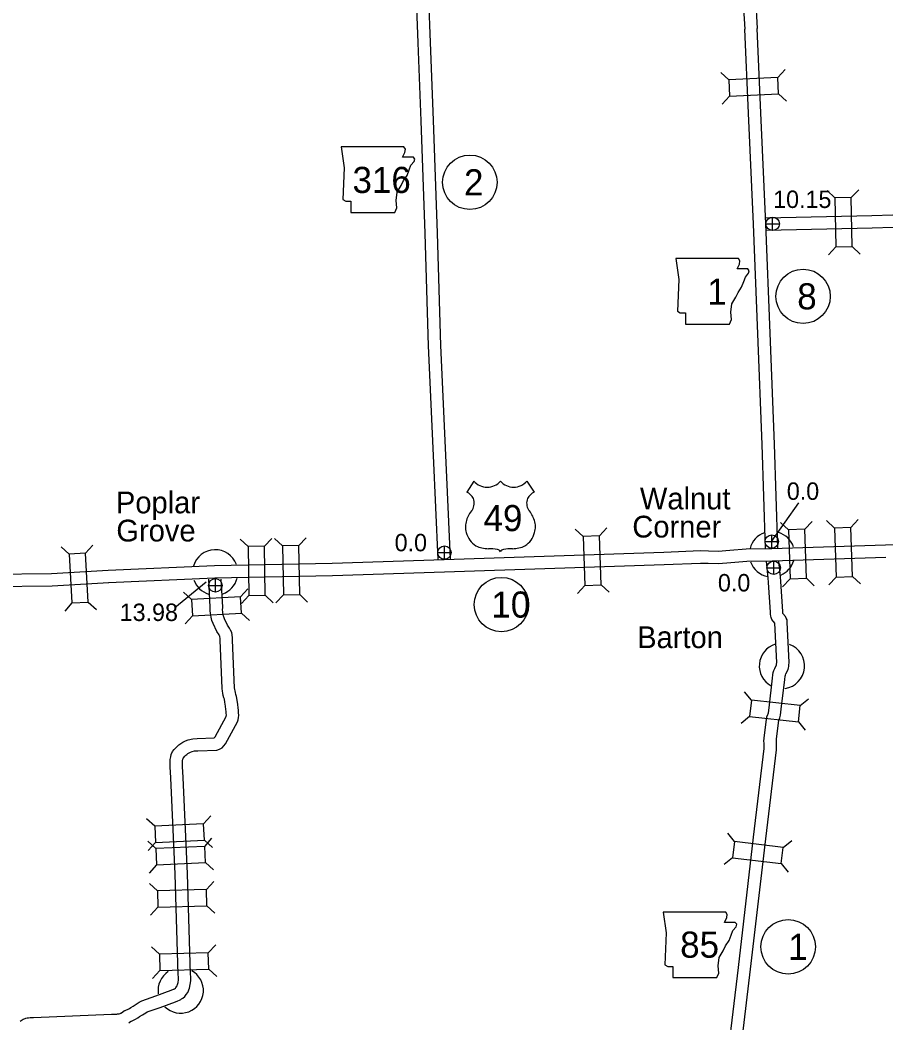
# Model space of a CAD drawing. Extents: x -939622 to -934222, y 1383701 to 1385301.
# Drawn here: x -935826.6 to -935763.6, y 1384033.1 to 1384106.1 of the extents above; entities that cross this region are included whole.
import ezdxf

# ---------------------------------------------------------------- set-up
doc = ezdxf.new("R2010")
doc.units = 0
for name, color, linetype in [('Level 10', 7, 'Continuous'), ('Level 15', 7, 'Continuous'), ('Level 20', 7, 'Continuous'), ('Level 21', 7, 'Continuous'), ('Level 22', 7, 'Continuous'), ('Level 24', 7, 'Continuous'), ('Level 25', 7, 'Continuous'), ('Level 26', 7, 'Continuous'), ('Level 27', 7, 'Continuous')]:
    doc.layers.add(name, color=color, linetype=linetype)

msp = doc.modelspace()

# ---------------------------------------------------------------- linework, layer by layer
at = {"layer": 'Level 10'}
for points in [[(-935774.237, 1384115.055), (-935773.997, 1384107.704), (-935773.868, 1384105.431)], [(-935773.338, 1384115.111), (-935773.098, 1384107.744), (-935772.969, 1384105.482)], [(-935797.116, 1384114.281), (-935797.116, 1384114.271), (-935796.897, 1384107.678), (-935796.77, 1384104.464)], [(-935798.016, 1384114.251), (-935798.015, 1384114.226), (-935797.797, 1384107.646), (-935797.669, 1384104.428)], [(-935772.353, 1384067.639), (-935772.602, 1384075.207), (-935772.91, 1384083.272), (-935773.241, 1384091.235), (-935773.588, 1384099.309), (-935773.868, 1384105.436)], [(-935771.454, 1384067.666), (-935771.703, 1384075.239), (-935772.011, 1384083.308), (-935772.342, 1384091.273), (-935772.689, 1384099.348), (-935772.969, 1384105.477)], [(-935797.669, 1384104.43), (-935797.46, 1384098.764), (-935797.146, 1384090.566), (-935796.911, 1384082.383), (-935796.547, 1384074.399), (-935796.21, 1384066.836)], [(-935796.77, 1384104.463), (-935796.56, 1384098.798), (-935796.247, 1384090.596), (-935796.012, 1384082.416), (-935795.648, 1384074.439), (-935795.311, 1384066.89)], [(-935772.345, 1384091.713), (-935764.621, 1384091.871)], [(-935764.625, 1384091.871), (-935756.982, 1384092.107)], [(-935772.318, 1384090.814), (-935764.602, 1384090.971)], [(-935764.598, 1384090.971), (-935756.947, 1384091.207)], [(-935774.335, 1384037.15), (-935773.234, 1384046.628), (-935772.461, 1384053.102), (-935772.446, 1384053.233), (-935772.446, 1384053.268), (-935772.45, 1384053.37), (-935772.465, 1384053.505), (-935772.47, 1384053.611), (-935772.448, 1384053.86), (-935772.258, 1384055.401), (-935772.183, 1384055.57), (-935772.16, 1384055.618), (-935772.142, 1384055.687), (-935772.103, 1384056.059), (-935771.848, 1384058.212), (-935771.816, 1384058.463), (-935771.795, 1384058.63), (-935771.752, 1384058.759), (-935771.682, 1384058.913), (-935771.553, 1384059.177), (-935771.552, 1384059.179), (-935771.549, 1384059.196), (-935771.546, 1384059.23), (-935771.539, 1384059.348), (-935771.675, 1384062.212), (-935771.903, 1384062.472), (-935771.95, 1384062.618), (-935771.968, 1384062.709), (-935771.993, 1384062.872), (-935772.002, 1384063.006), (-935772.148, 1384065.169), (-935772.174, 1384065.504), (-935772.291, 1384066.698)], [(-935773.441, 1384037.047), (-935772.34, 1384046.523), (-935771.567, 1384052.999), (-935771.546, 1384053.183), (-935771.546, 1384053.287), (-935771.553, 1384053.438), (-935771.567, 1384053.572), (-935771.568, 1384053.592), (-935771.553, 1384053.766), (-935771.381, 1384055.157), (-935771.363, 1384055.197), (-935771.309, 1384055.314), (-935771.255, 1384055.526), (-935771.208, 1384055.958), (-935770.955, 1384058.103), (-935770.923, 1384058.349), (-935770.913, 1384058.43), (-935770.868, 1384058.528), (-935770.715, 1384058.842), (-935770.679, 1384058.956), (-935770.657, 1384059.066), (-935770.648, 1384059.16), (-935770.638, 1384059.344), (-935770.777, 1384062.286), (-935770.79, 1384062.453), (-935770.843, 1384062.579), (-935770.898, 1384062.691), (-935771.088, 1384062.907), (-935771.098, 1384062.972), (-935771.104, 1384063.067), (-935771.25, 1384065.234), (-935771.277, 1384065.583), (-935771.389, 1384066.725)], [(-935815.314, 1384035.654), (-935815.276, 1384035.714), (-935815.196, 1384035.817), (-935815.151, 1384035.916), (-935815.124, 1384036.074), (-935815.096, 1384036.262), (-935815.095, 1384036.457), (-935815.106, 1384036.644), (-935815.321, 1384043.941), (-935815.653, 1384050.947), (-935815.697, 1384051.762), (-935815.695, 1384052.093), (-935815.685, 1384052.289), (-935815.649, 1384052.497), (-935815.613, 1384052.655), (-935815.515, 1384052.869), (-935815.402, 1384053.008), (-935815.29, 1384053.131), (-935815.189, 1384053.241), (-935815.064, 1384053.354), (-935814.93, 1384053.459), (-935814.781, 1384053.55), (-935814.585, 1384053.643), (-935814.375, 1384053.727), (-935814.053, 1384053.806), (-935813.727, 1384053.827), (-935812.487, 1384053.863), (-935812.47, 1384053.882), (-935812.419, 1384053.943), (-935811.62, 1384055.423), (-935811.615, 1384055.459), (-935811.606, 1384055.527), (-935811.612, 1384055.655), (-935811.62, 1384055.782), (-935811.64, 1384055.932), (-935811.671, 1384056.173), (-935811.709, 1384056.47), (-935811.75, 1384056.677), (-935811.777, 1384056.78), (-935811.827, 1384056.952), (-935811.858, 1384057.112), (-935811.887, 1384057.273), (-935811.898, 1384057.465), (-935812.065, 1384060.983), (-935812.058, 1384061.122), (-935812.069, 1384061.213), (-935812.079, 1384061.263), (-935812.095, 1384061.299), (-935812.139, 1384061.373), (-935812.301, 1384061.616), (-935812.57, 1384062.181), (-935812.656, 1384062.405), (-935812.682, 1384062.53), (-935812.709, 1384062.652), (-935812.737, 1384062.789), (-935812.761, 1384062.935), (-935812.784, 1384063.118), (-935812.773, 1384063.376), (-935812.882, 1384065.408)], [(-935814.635, 1384035.046), (-935814.54, 1384035.195), (-935814.421, 1384035.348), (-935814.284, 1384035.648), (-935814.235, 1384035.932), (-935814.197, 1384036.193), (-935814.195, 1384036.48), (-935814.206, 1384036.684), (-935814.422, 1384043.975), (-935814.754, 1384050.993), (-935814.797, 1384051.783), (-935814.795, 1384052.067), (-935814.788, 1384052.19), (-935814.766, 1384052.322), (-935814.756, 1384052.365), (-935814.745, 1384052.39), (-935814.721, 1384052.42), (-935814.626, 1384052.523), (-935814.555, 1384052.601), (-935814.484, 1384052.665), (-935814.415, 1384052.719), (-935814.353, 1384052.757), (-935814.225, 1384052.817), (-935814.099, 1384052.868), (-935813.916, 1384052.913), (-935813.685, 1384052.928), (-935812.293, 1384052.969), (-935812.094, 1384053.032), (-935811.92, 1384053.15), (-935811.791, 1384053.291), (-935811.67, 1384053.436), (-935810.803, 1384055.041), (-935810.744, 1384055.173), (-935810.722, 1384055.345), (-935810.704, 1384055.489), (-935810.713, 1384055.703), (-935810.724, 1384055.87), (-935810.747, 1384056.05), (-935810.778, 1384056.288), (-935810.82, 1384056.614), (-935810.872, 1384056.878), (-935810.909, 1384057.02), (-935810.951, 1384057.164), (-935810.973, 1384057.278), (-935810.992, 1384057.38), (-935811, 1384057.513), (-935811.164, 1384060.98), (-935811.155, 1384061.154), (-935811.18, 1384061.357), (-935811.216, 1384061.535), (-935811.293, 1384061.711), (-935811.378, 1384061.854), (-935811.517, 1384062.062), (-935811.742, 1384062.536), (-935811.79, 1384062.661), (-935811.802, 1384062.716), (-935811.828, 1384062.839), (-935811.852, 1384062.952), (-935811.87, 1384063.063), (-935811.882, 1384063.156), (-935811.872, 1384063.38), (-935811.981, 1384065.406)], [(-935776.498, 1384019.021), (-935774.335, 1384037.152)], [(-935775.608, 1384018.879), (-935773.441, 1384037.045)], [(-935819.031, 1384033.999), (-935818.662, 1384034.176), (-935818.559, 1384034.244), (-935818.4, 1384034.355), (-935818.165, 1384034.478), (-935817.951, 1384034.627), (-935817.753, 1384034.744), (-935816.734, 1384035.106), (-935815.621, 1384035.508), (-935815.451, 1384035.571), (-935815.421, 1384035.583), (-935815.388, 1384035.609), (-935815.306, 1384035.661), (-935815.314, 1384035.654)], [(-935818.563, 1384033.225), (-935818.217, 1384033.391), (-935818.053, 1384033.5), (-935817.932, 1384033.584), (-935817.697, 1384033.707), (-935817.464, 1384033.87), (-935817.371, 1384033.925), (-935816.431, 1384034.259), (-935815.312, 1384034.663), (-935815.128, 1384034.731), (-935815.012, 1384034.777), (-935814.923, 1384034.831), (-935814.87, 1384034.871), (-935814.78, 1384034.929), (-935814.635, 1384035.046)], [(-935819.031, 1384033.999), (-935819.241, 1384033.842), (-935819.262, 1384033.826), (-935819.267, 1384033.823), (-935819.298, 1384033.809), (-935819.324, 1384033.8), (-935819.359, 1384033.79), (-935819.427, 1384033.774), (-935819.498, 1384033.763), (-935819.565, 1384033.751), (-935819.612, 1384033.748), (-935819.969, 1384033.729), (-935825.642, 1384033.5), (-935825.727, 1384033.494), (-935825.877, 1384033.495), (-935826.018, 1384033.481), (-935826.113, 1384033.463), (-935826.227, 1384033.439), (-935826.386, 1384033.38), (-935826.538, 1384033.284), (-935826.624, 1384033.222)], [(-935818.563, 1384033.225), (-935818.704, 1384033.119)]]:
    msp.add_lwpolyline(points, dxfattribs=at)
at = {"layer": 'Level 15'}
for points in [[(-935763.621, 1384067.917), (-935756.03, 1384068.186), (-935748.251, 1384068.58), (-935745.821, 1384068.663), (-935745.554, 1384068.626), (-935745.375, 1384068.56), (-935745.193, 1384068.5), (-935744.945, 1384068.462), (-935744.766, 1384068.413), (-935744.648, 1384068.406), (-935744.464, 1384068.405), (-935744.288, 1384068.408), (-935744.145, 1384068.427), (-935743.998, 1384068.465), (-935743.764, 1384068.535), (-935743.486, 1384068.595), (-935743.242, 1384068.647), (-935742.933, 1384068.667), (-935742.196, 1384068.741), (-935739.65, 1384068.835)], [(-935820.212, 1384066.06), (-935812.475, 1384066.397), (-935803.891, 1384066.575), (-935795.755, 1384066.846), (-935787.733, 1384067.118), (-935779.756, 1384067.381), (-935777.095, 1384067.486), (-935776.515, 1384067.48), (-935775.797, 1384067.45), (-935774.948, 1384067.521), (-935773.77, 1384067.614), (-935771.9, 1384067.652), (-935763.619, 1384067.917)], [(-935820.173, 1384065.16), (-935812.446, 1384065.498), (-935803.867, 1384065.676), (-935795.725, 1384065.947), (-935787.702, 1384066.218), (-935779.724, 1384066.482), (-935777.082, 1384066.586), (-935776.539, 1384066.58), (-935775.778, 1384066.548), (-935774.875, 1384066.624), (-935773.725, 1384066.715), (-935771.877, 1384066.752), (-935763.59, 1384067.017)], [(-935828.702, 1384065.766), (-935824.326, 1384065.829), (-935820.217, 1384066.059)], [(-935828.695, 1384064.866), (-935824.295, 1384064.929), (-935820.167, 1384065.161)]]:
    msp.add_lwpolyline(points, dxfattribs=at)
at = {"layer": 'Level 20'}
for p, q in [((-935775.033, 1384101.737), (-935775.618, 1384102.271)), ((-935771.472, 1384101.9), (-935770.938, 1384102.485)), ((-935774.978, 1384100.55), (-935775.512, 1384099.965)), ((-935771.418, 1384100.713), (-935770.833, 1384100.179)), ((-935767.301, 1384093.148), (-935767.873, 1384093.697)), ((-935766.113, 1384093.173), (-935765.565, 1384093.744)), ((-935767.228, 1384089.585), (-935767.777, 1384089.014)), ((-935766.041, 1384089.609), (-935765.469, 1384089.061)), ((-935785.628, 1384068.52), (-935786.207, 1384069.061)), ((-935784.441, 1384068.559), (-935783.9, 1384069.138)), ((-935770.685, 1384069), (-935771.263, 1384069.542)), ((-935769.498, 1384069.038), (-935768.956, 1384069.615)), ((-935767.33, 1384069.131), (-935767.908, 1384069.673)), ((-935766.142, 1384069.169), (-935765.601, 1384069.746)), ((-935810.024, 1384067.782), (-935810.594, 1384068.331)), ((-935808.836, 1384067.804), (-935808.287, 1384068.374)), ((-935807.524, 1384067.832), (-935808.096, 1384068.381)), ((-935806.336, 1384067.857), (-935805.788, 1384068.429)), ((-935823.036, 1384067.236), (-935823.625, 1384067.765)), ((-935821.85, 1384067.301), (-935821.321, 1384067.89)), ((-935770.571, 1384065.438), (-935771.113, 1384064.86)), ((-935769.384, 1384065.475), (-935768.806, 1384064.934)), ((-935767.216, 1384065.569), (-935767.758, 1384064.991)), ((-935766.029, 1384065.606), (-935765.451, 1384065.065)), ((-935810.578, 1384064.119), (-935810.049, 1384064.708)), ((-935785.511, 1384064.958), (-935786.052, 1384064.38)), ((-935784.323, 1384064.997), (-935783.745, 1384064.456)), ((-935814.136, 1384063.927), (-935814.726, 1384064.456)), ((-935809.957, 1384064.218), (-935810.506, 1384063.648)), ((-935808.769, 1384064.241), (-935808.199, 1384063.691)), ((-935807.45, 1384064.269), (-935807.998, 1384063.698)), ((-935806.262, 1384064.294), (-935805.691, 1384063.746)), ((-935822.843, 1384063.678), (-935823.372, 1384063.088)), ((-935821.657, 1384063.742), (-935821.067, 1384063.213)), ((-935814.072, 1384062.741), (-935814.601, 1384062.151)), ((-935810.514, 1384062.933), (-935809.924, 1384062.404)), ((-935773.385, 1384056.597), (-935773.882, 1384057.214)), ((-935769.841, 1384056.219), (-935769.224, 1384056.716)), ((-935773.511, 1384055.416), (-935774.127, 1384054.919)), ((-935769.967, 1384055.037), (-935769.47, 1384054.421)), ((-935816.82, 1384047.436), (-935817.406, 1384047.969)), ((-935813.26, 1384047.605), (-935812.727, 1384048.191)), ((-935813.204, 1384046.419), (-935812.618, 1384045.886)), ((-935813.183, 1384045.973), (-935812.65, 1384046.559)), ((-935774.61, 1384046.316), (-935775.101, 1384046.938)), ((-935816.743, 1384045.805), (-935817.329, 1384046.337)), ((-935816.764, 1384046.25), (-935817.297, 1384045.664)), ((-935771.071, 1384045.898), (-935770.449, 1384046.388)), ((-935774.75, 1384045.136), (-935775.371, 1384044.646)), ((-935816.687, 1384044.618), (-935817.22, 1384044.032)), ((-935813.127, 1384044.787), (-935812.541, 1384044.254)), ((-935771.21, 1384044.718), (-935770.72, 1384044.096)), ((-935816.618, 1384042.734), (-935817.194, 1384043.277)), ((-935813.056, 1384042.839), (-935812.512, 1384043.415)), ((-935816.583, 1384041.546), (-935817.126, 1384040.97)), ((-935813.021, 1384041.652), (-935812.444, 1384041.108)), ((-935816.481, 1384038.129), (-935817.056, 1384038.673)), ((-935812.918, 1384038.227), (-935812.374, 1384038.802)), ((-935816.448, 1384036.941), (-935816.993, 1384036.366)), ((-935812.886, 1384037.039), (-935812.31, 1384036.495))]:
    msp.add_line(p, q, dxfattribs=at)
for points in [[(-935771.472, 1384101.9), (-935775.033, 1384101.737), (-935774.978, 1384100.55), (-935771.418, 1384100.713)], [(-935766.041, 1384089.609), (-935766.113, 1384093.173), (-935767.301, 1384093.148), (-935767.228, 1384089.585)], [(-935770.685, 1384069), (-935770.571, 1384065.438), (-935769.384, 1384065.475), (-935769.498, 1384069.038)], [(-935767.33, 1384069.131), (-935767.216, 1384065.569), (-935766.029, 1384065.606), (-935766.142, 1384069.169)], [(-935784.323, 1384064.997), (-935784.441, 1384068.559), (-935785.628, 1384068.52), (-935785.511, 1384064.958)], [(-935808.769, 1384064.241), (-935808.836, 1384067.804), (-935810.024, 1384067.782), (-935809.957, 1384064.218)], [(-935807.524, 1384067.832), (-935807.45, 1384064.269), (-935806.262, 1384064.294), (-935806.336, 1384067.857)], [(-935821.657, 1384063.742), (-935821.85, 1384067.301), (-935823.036, 1384067.236), (-935822.843, 1384063.678)], [(-935810.578, 1384064.119), (-935814.136, 1384063.927), (-935814.072, 1384062.741), (-935810.514, 1384062.933)], [(-935773.511, 1384055.416), (-935769.967, 1384055.037), (-935769.841, 1384056.219), (-935773.385, 1384056.597)], [(-935813.26, 1384047.605), (-935816.82, 1384047.436), (-935816.764, 1384046.25), (-935813.204, 1384046.419)], [(-935813.183, 1384045.973), (-935816.743, 1384045.805), (-935816.687, 1384044.618), (-935813.127, 1384044.787)], [(-935774.75, 1384045.136), (-935771.21, 1384044.718), (-935771.071, 1384045.898), (-935774.61, 1384046.316)], [(-935816.583, 1384041.546), (-935813.021, 1384041.652), (-935813.056, 1384042.839), (-935816.618, 1384042.734)], [(-935812.918, 1384038.227), (-935816.481, 1384038.129), (-935816.448, 1384036.941), (-935812.886, 1384037.039)]]:
    msp.add_lwpolyline(points, close=True, dxfattribs=at)
at = {"layer": 'Level 21'}
for points in [[(-935803.246, 1384096.868), (-935803.017, 1384095.345), (-935803.119, 1384093.036), (-935802.916, 1384092.909), (-935802.535, 1384092.909), (-935802.535, 1384092.097), (-935799.338, 1384092.097), (-935799.186, 1384092.427), (-935799.236, 1384092.96), (-935799.16, 1384093.569), (-935798.881, 1384094.051), (-935798.703, 1384094.406), (-935798.45, 1384094.787), (-935798.297, 1384095.193), (-935798.17, 1384095.523), (-935797.942, 1384095.802), (-935797.891, 1384095.98), (-935797.993, 1384096.107), (-935798.78, 1384096.107), (-935798.602, 1384096.462), (-935798.576, 1384096.69), (-935798.682, 1384096.866)], [(-935778.89, 1384088.74), (-935778.661, 1384087.218), (-935778.763, 1384084.909), (-935778.56, 1384084.782), (-935778.179, 1384084.782), (-935778.179, 1384083.97), (-935774.981, 1384083.97), (-935774.829, 1384084.299), (-935774.88, 1384084.832), (-935774.804, 1384085.441), (-935774.525, 1384085.924), (-935774.347, 1384086.279), (-935774.093, 1384086.66), (-935773.941, 1384087.066), (-935773.814, 1384087.395), (-935773.586, 1384087.675), (-935773.535, 1384087.852), (-935773.636, 1384087.979), (-935774.423, 1384087.979), (-935774.246, 1384088.334), (-935774.22, 1384088.563), (-935774.325, 1384088.738)], [(-935779.808, 1384041.191), (-935779.579, 1384039.668), (-935779.681, 1384037.359), (-935779.478, 1384037.232), (-935779.097, 1384037.232), (-935779.097, 1384036.42), (-935775.9, 1384036.42), (-935775.747, 1384036.75), (-935775.798, 1384037.283), (-935775.722, 1384037.892), (-935775.443, 1384038.374), (-935775.265, 1384038.729), (-935775.011, 1384039.11), (-935774.859, 1384039.516), (-935774.732, 1384039.846), (-935774.504, 1384040.125), (-935774.453, 1384040.302), (-935774.555, 1384040.429), (-935775.341, 1384040.429), (-935775.164, 1384040.785), (-935775.138, 1384041.013), (-935775.244, 1384041.188)]]:
    msp.add_lwpolyline(points, close=True, dxfattribs=at)
at = {"layer": 'Level 22'}
for p, q in [((-935793.584, 1384072.553), (-935794.103, 1384071.75)), ((-935789.723, 1384072.553), (-935789.204, 1384071.75))]:
    msp.add_line(p, q, dxfattribs=at)
for centre, radius, start, end in [((-935792.617, 1384073.367), 1.264, 220.07504, 319.67012), ((-935790.69, 1384073.367), 1.264, 220.32988, 319.92496), ((-935794.782, 1384070.585), 1.349, 30.7809, 59.98827), ((-935794.485, 1384070.94), 0.925, 328.81046, 21.21077), ((-935788.822, 1384070.94), 0.925, 158.78923, 211.18954), ((-935788.526, 1384070.585), 1.349, 120.01173, 149.2191), ((-935792.067, 1384069.045), 2.157, 138.95648, 162.69135), ((-935791.241, 1384069.045), 2.157, 17.30865, 41.04352), ((-935792.779, 1384069.222), 1.426, 160.95764, 197.38186), ((-935790.528, 1384069.222), 1.426, 342.61814, 19.04236), ((-935792.547, 1384069.226), 1.65, 195.10743, 237.13119), ((-935790.761, 1384069.226), 1.65, 302.86881, 344.89257), ((-935792.516, 1384069.745), 2.118, 244.07708, 269.57785), ((-935792.467, 1384063.748), 3.88, 81.19416, 90.95387), ((-935791.982, 1384067.226), 0.372, 28.03422, 72.98637), ((-935791.325, 1384067.226), 0.372, 107.01363, 151.96578), ((-935790.84, 1384063.748), 3.88, 89.04613, 98.80584), ((-935790.791, 1384069.745), 2.118, 270.42215, 295.92292)]:
    msp.add_arc(centre, radius, start, end, dxfattribs=at)
at = {"layer": 'Level 24'}
for centre, start, end in [((-935771.887, 1384067.226), 109.50244, 165.14136), ((-935771.887, 1384067.226), 19.17902, 72.64597), ((-935812.415, 1384065.905), 20.28257, 163.73979), ((-935771.887, 1384067.226), 199.50241, 259.59231), ((-935771.887, 1384067.226), 293.05131, 343.73982), ((-935812.415, 1384065.905), 289.50241, 344.84591), ((-935812.415, 1384065.905), 200.28255, 252.64596), ((-935771.161, 1384059.101), 107.35398, 241.38954), ((-935771.161, 1384059.101), 277.96965, 70.49755), ((-935814.926, 1384035.484), 225.78486, 60.83239), ((-935814.926, 1384035.484), 123.36635, 188.13009)]:
    msp.add_arc(centre, 1.65, start, end, dxfattribs=at)
at = {"layer": 'Level 25'}
msp.add_line((-935771.926, 1384068.154), (-935769.938, 1384070.976), dxfattribs=at)
msp.add_lwpolyline([(-935815.355, 1384063.362), (-935813.076, 1384065.211)], dxfattribs=at)
at = {"layer": 'Level 26'}
for p, q in [((-935771.837, 1384090.781), (-935771.837, 1384091.756)), ((-935772.324, 1384091.269), (-935771.349, 1384091.269)), ((-935771.899, 1384067.66), (-935771.899, 1384068.635)), ((-935795.732, 1384066.856), (-935795.732, 1384067.831)), ((-935772.386, 1384068.147), (-935771.411, 1384068.147)), ((-935796.22, 1384067.343), (-935795.245, 1384067.343)), ((-935772.25, 1384066.243), (-935771.275, 1384066.243)), ((-935771.763, 1384065.756), (-935771.763, 1384066.731)), ((-935812.406, 1384064.475), (-935812.406, 1384065.45)), ((-935812.894, 1384064.962), (-935811.919, 1384064.962))]:
    msp.add_line(p, q, dxfattribs=at)
for centre in [(-935771.837, 1384091.269), (-935771.899, 1384068.147), (-935795.732, 1384067.343), (-935771.763, 1384066.243), (-935812.406, 1384064.962)]:
    msp.add_circle(centre, 0.487, dxfattribs=at)
at = {"layer": 'Level 27'}
for centre in [(-935793.879, 1384094.285), (-935769.622, 1384085.99), (-935791.581, 1384063.563), (-935770.709, 1384038.663)]:
    msp.add_circle(centre, 1.98, dxfattribs=at)

# ---------------------------------------------------------------- texts
at = {"layer": 'Level 21'}
for s, height, p in [('316', 1.9008, (-935802.422, 1384093.509)), ('1', 1.901, (-935776.598, 1384085.383)), ('85', 1.9008, (-935778.568, 1384037.87))]:
    msp.add_text(s, height=height, dxfattribs=at).set_placement(p)
at = {"layer": 'Level 22'}
msp.add_text('49', height=1.9008, dxfattribs=at).set_placement((-935792.881, 1384068.905))
at = {"layer": 'Level 24'}
for s, p in [('Walnut', (-935781.501, 1384070.488)), ('Poplar', (-935819.643, 1384070.202)), ('Grove', (-935819.613, 1384068.155)), ('Corner', (-935782.054, 1384068.441)), ('Barton', (-935781.701, 1384060.397))]:
    msp.add_text(s, height=1.584, dxfattribs=at).set_placement(p)
at = {"layer": 'Level 25'}
for s, p in [('10.15', (-935771.801, 1384092.418)), ('0.0', (-935770.806, 1384071.184)), ('0.0', (-935799.354, 1384067.44)), ('0.0', (-935775.822, 1384064.519)), ('13.98', (-935819.37, 1384062.368))]:
    msp.add_text(s, height=1.2672, dxfattribs=at).set_placement(p)
at = {"layer": 'Level 27'}
for s, height, p in [('2', 1.901, (-935794.304, 1384093.334)), ('8', 1.901, (-935770.047, 1384085.04)), ('10', 1.9008, (-935792.314, 1384062.613)), ('1', 1.901, (-935770.709, 1384037.712))]:
    msp.add_text(s, height=height, dxfattribs=at).set_placement(p)

doc.saveas('drawing.dxf')
